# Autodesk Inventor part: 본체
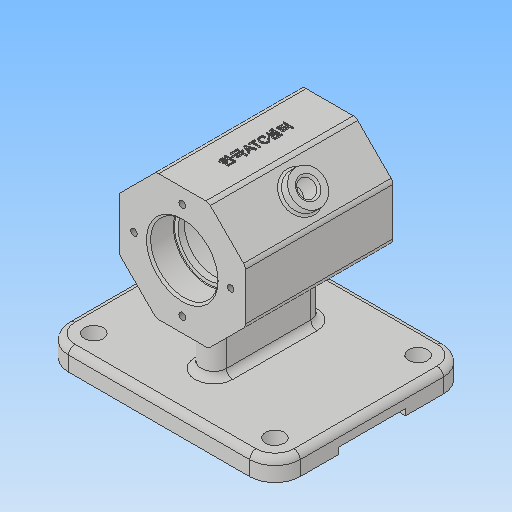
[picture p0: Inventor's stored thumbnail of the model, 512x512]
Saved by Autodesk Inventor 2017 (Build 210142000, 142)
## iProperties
Part Number: 본체
Material: 일반
Document SubType Name: Modeling
Designer: MRC
Density: 1 g/cm^3
Appearance: 기본값
Mass: 207.094 g
Surface Area: 567.647 cm^2
Volume: 207.094 cm^3
Author: MRC
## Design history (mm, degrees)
sketch "스케치1"
  geometry: L1 (30, 12.426)-(30, -12.426); L2 (30, -12.426)-(12.426, -30); L3 (12.426, -30)-(-12.426, -30); L4 (-12.426, -30)-(-30, -12.426); L5 (-30, -12.426)-(-30, 12.426); L6 (-30, 12.426)-(-12.426, 30); L7 (-12.426, 30)-(12.426, 30); L8 (12.426, 30)-(30, 12.426); 2 further points
  constraints: 16 end point, 1 coincident, 1 horizontal, 17 other
  dimensions: "d1" = 60 distance between parallel lines of L3 L7
extrude "돌출1" new body sketch "스케치1" stored distance "d2" = 70; taper "d3" = 0 deg
sketch "스케치3"
  geometry: 2 further points
  constraints: 1 vertical alignment
  dimensions: "d4" = 23 distance of point (0, 0) point (0, 23)
hole "구멍1" sketch "스케치3" at (0, 23) diameter "d5" = 3.242; stored, may be unused: countersink angle "d9" = 90 deg, drill point angle "d11" = 118 deg; dims "d6" = 8, "d7" = 32, "d8" = 12, "d10" = 10
sketch "스케치4"
  geometry: 2 further points
  constraints: 1 coincident
hole "구멍2" sketch "스케치4" at (0, 0) diameter "d12" = 28; stored, may be unused: countersink angle "d16" = 90 deg, drill point angle "d18" = 0 deg; dims "d13" = 8, "d14" = 32, "d15" = 12, "d17" = 10
sketch "스케치5"
  geometry: C1 r 25 at (0, 0); 1 further point
  constraints: 1 centre point, 1 coincident
  dimensions: "d19" = 50 diameter of C1
extrude "돌출2" cut sketch "스케치5" stored distance "d20" = 40; taper "d21" = 0 deg
sketch "스케치7"
  geometry: C1 r 8 at (-12.426, 35); 1 further point
  constraints: 1 centre point, 1 coincident
  dimensions: "d27" = 16 diameter of C1
extrude "돌출3" join sketch "스케치7" distance "d28" = 5; taper "d29" = 0 deg
hole "구멍3" diameter "d32" = 8; stored, may be unused: countersink angle "d36" = 90 deg, drill point angle "d38" = 0 deg; dims "d30" = 10, "d31" = 10, "d33" = 8, "d34" = 32, "d35" = 12, "d37" = 24
sketch "스케치8"
  geometry: L1 (-55, -52)-(55, -52); L2 (55, -52)-(55, -62); L3 (55, -62)-(-55, -62); L4 (-55, -62)-(-55, -52); 2 further points
  constraints: 8 end point, 2 parallel, 1 horizontal, 1 midpoint, 1 perpendicular, 1 vertical alignment
  dimensions: "d39" = 110 distance of L2.end L3.end; "d40" = 10 distance of L1.end L2.end; "d41" = 62 vertical distance of L3.end point (0, 0)
extrude "돌출4" join sketch "스케치8" stored distance "d42" = 92; taper "d43" = 0 deg
sketch "스케치9"
  geometry: L1 (55, 66)-(55, 26); L2 (61, 66)-(61, 26); L3 (49, 26)-(49, 66); A1 r 6 centre (55, 66) between (61, 66) and (49, 66); A2 r 6 centre (55, 26) between (49, 26) and (61, 26); 2 further points
  constraints: 8 end point, 4 point on circle, 4 tangent, 2 centre point, 1 coincident, 1 midpoint, 1 parallel, 1 vertical
  dimensions: "d44" = 40 distance of L1.end L1.start; "d45" = 12 distance between parallel lines of L2 L3
extrude "돌출5" join sketch "스케치9" stored distance "d46" = 92; taper "d47" = 0 deg
fillet "모깎기1" dims "d48" = 12
sketch "스케치10"
  geometry: L1 (-12, 80)-(-12, 12) reference; L2 (86, 0)-(0, 0) reference; L3 (98, 12)-(98, 80) reference; L4 (0, 92)-(86, 92) reference; L5 (37, 26)-(37, 66) reference; L6 (49, 66)-(49, 26) reference; A1 r 12 centre (0, 80) between (0, 92) and (-12, 80) reference; A2 r 12 centre (0, 12) between (-12, 12) and (0, 0) reference; A3 r 12 centre (86, 12) between (86, 0) and (98, 12) reference; A4 r 12 centre (86, 80) between (98, 80) and (86, 92) reference; A5 r 6 centre (43, 26) between (37, 26) and (49, 26) reference; A6 r 6 centre (43, 66) between (49, 66) and (37, 66) reference; 5 further points
  constraints: 4 coincident
hole "구멍4" sketch "스케치10" at (0, 80), (0, 12), (86, 80), (86, 12) diameter "d49" = 9; stored, may be unused: countersink angle "d53" = 90 deg, drill point angle "d55" = 0 deg; dims "d50" = 8, "d51" = 32, "d52" = 12, "d54" = 24
sketch "스케치11"
  geometry: L1 (-68, 0)-(0, 0) reference; L2 (-50, 0)-(-50, 3); L3 (-50, 3)-(-18, 3); L4 (-18, 3)-(-18, 0); 2 further points
  constraints: 6 end point, 3 perpendicular, 2 point on line, 1 midpoint, 1 vertical alignment
  dimensions: "d56" = 32 distance of L2.end L3.end; "d57" = 3 distance of L3.end L4.end
extrude "돌출6" cut sketch "스케치11" stored distance "d58" = 92; taper "d59" = 0 deg
sketch "스케치12"
  geometry: L1 (-17.574, 0)-(-17.574, 70) reference; 2 further points
  constraints: 1 coincident, 1 other
  dimensions: "d60" = 30 distance from line of point (12.426, 35) L1
feature "엠보싱1" sketch "스케치12" dims "d1" = 60, "d61" = 0.5, "d62" = 0
fillet "모깎기2" dims "d63" = 3
fillet "모깎기3" dims "d64" = 3
fillet "모깎기4" dims "d65" = 1
fillet "모깎기5" dims "d66" = 0.3
fillet "모깎기6" dims "d67" = 3
chamfer "모따기1" distance "d68" = 1; stored, may be unused: second distance "d69" = 2, angle "d70" = 45 deg
node "솔리드1"
pattern_circular "원형 패턴1" dims angle "d23" = 360 deg
mirror "미러1"
node "투영된 루프1"
